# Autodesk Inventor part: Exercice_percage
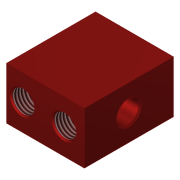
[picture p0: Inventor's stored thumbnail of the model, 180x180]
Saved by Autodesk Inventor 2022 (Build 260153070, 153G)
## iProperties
Created: 2018-06
Part Number: Exercice_percage
Material: Aluminium 6061
Document SubType Name: Modeling
Designer: Fabian Perrée
Density: 2.7 g/cm^3
Appearance: Anodisé - Rouge
Mass: 125.414 g
Surface Area: 130.388 cm^2
Volume: 46.4496 cm^3
Author: Fabian Perrée
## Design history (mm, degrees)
sketch "Esquisse1"
  geometry: L1 (-21, 24)-(21, 24); L2 (21, 24)-(21, -24); L3 (21, -24)-(-21, -24); L4 (-21, -24)-(-21, 24); L5 (-21, 24)-(21, -24); L6 (21, 24)-(-21, -24); 1 further point
  constraints: 12 end point, 2 midpoint, 2 parallel, 1 horizontal, 1 perpendicular
  dimensions: "d0" = 48 distance of L1.end L2.end; "d1" = 42 distance of L2.end L3.end
extrude "Extrusion1" new body sketch "Esquisse1" stored distance "d2" = 28; taper "d3" = 0 deg
sketch "Esquisse2"
  geometry: L1 (21, 24)-(21, -24) reference; L2 (21, 0)-(-21, 0); L3 (-21, 24)-(21, 24) reference; L4 (21, -24)-(-21, -24) reference; L5 (0, -24)-(0, 24); L6 (12.5, 24)-(12.5, 0); L7 (18.5, 24)-(18.5, 13); L8 (18.5, 13)-(17.75, 13); L9 (16.25, 11.5)-(16.25, 10); L10 (16.25, 10)-(14.5, 10); L11 (14.5, 10)-(14.5, 0); L12 (21, -6)-(8.5, -6); L13 (8.5, -6)-(8.5, -5.25); L14 (8.5, -5.25)-(5.5, -5.25); L15 (5.5, -5.25)-(5.5, -2.5); L16 (5.5, -2.5)-(0.5, -2.5); L17 (0.5, -2.5)-(0.5, -2); L18 (0.5, -2)-(-0.5, -2); L19 (-0.5, -2)-(-0.5, -6); L20 (-0.5, -6)-(-21, -6); L21 (-21, -24)-(-21, 24) reference; L22 (21, -6)-(21, 0); L23 (-21, -6)-(-21, 0); A1 r 1.5 centre (17.75, 11.5) between (17.75, 13) and (16.25, 11.5); 2 further points
  constraints: 38 end point, 12 perpendicular, 8 point on line, 3 horizontal, 3 midpoint, 2 point on circle, 2 tangent, 1 centre point, 1 collinear, 1 parallel, 1 vertical
  dimensions: "d6" = 12 diameter of L7 L6; "d7" = 8.5 distance between parallel lines of L1 L6; "d8" = 7.5 diameter of L9 L6; "d9" = 4 diameter of L11 L6; "d10" = 11 distance of L7.start L7.end; "d11" = 3 distance of point (16.25, 13) L9.end; "d12" = 1.5 radius of A1; "d19" = 12 diameter of L12 L2; "d20" = 10.5 diameter of L14 L2; "d21" = 5 diameter of L16 L2; "d22" = 4 diameter of L18 L2; "d23" = 1 distance of L17.end L18.end; "d24" = 12 diameter of L20 L2; "d25" = 12.5 distance of L12.start L12.end; "d26" = 15.5 distance between parallel lines of L15 L1; "d27" = 20.5 distance of L19.end L20.end
revolve "Révolution1" stored, may be unused: angle "d35" = 90 deg
sketch "Esquisse3"
  geometry: C1 r 6 at (8.5, -14) reference; 2 further points
  constraints: 1 horizontal alignment
  dimensions: "d36" = 22.5 distance of C1.centre point (31, -14)
sketch "Esquisse4"
  geometry: L1 (42, 0)-(42, -28) reference; 2 further points
  constraints: 1 horizontal alignment
  dimensions: "d37" = 18 distance from line of L1 point (24, -14)
feature "Filetage1" dims "d42" = 10, "d43" = 0
feature "Réseau basé sur une esquisse1"
feature "Réseau basé sur une esquisse2"
revolve "Révolution2" stored, may be unused: angle "d38" = 90 deg
feature "Filetage2" dims "d47" = 10, "d48" = 0
chamfer "Chanfrein4" distance "d75" = 0.75; stored, may be unused: second distance "d76" = 2, angle "d77" = 45 deg
node "Solide1"
